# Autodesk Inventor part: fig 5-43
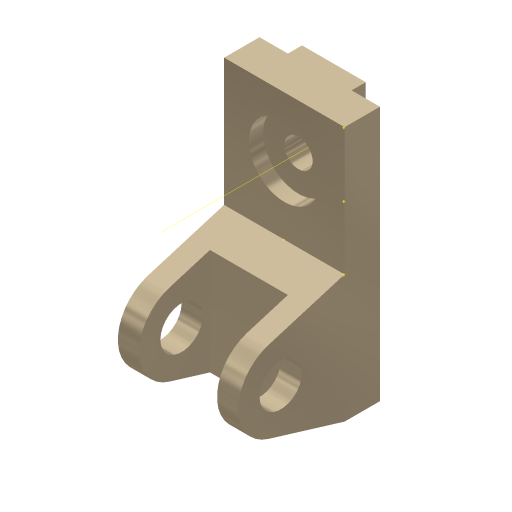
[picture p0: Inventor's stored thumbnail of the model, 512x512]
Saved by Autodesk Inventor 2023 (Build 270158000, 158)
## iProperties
Created: 2001-11
Part Number: fig 5-43
Document SubType Name: Modeling
Designer: Renu Muthoo
Density: 1 g/cm^3
Material: Generic
Appearance: Metal-Titanium (Polished)
Control State: 0
Master: False
Checked Out: False
Shininess: 65.0
Angle Display Precision: 2
Document Length Units: 11269
Document Angle Units: 11279
Document Time Units: 11290
Document Mass Units: 11283
Document Length Units Precision: 3
Document Angle Units Precision: 2
Density: 0.0
Volumn: 0.0
Area: 0.0
PropertySet Name: Model Information
Author: Renu Muthoo
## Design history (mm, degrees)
node "Sketch1"
sketch "Sketch2"
  geometry: L1 (33.257, 104.664)-(33.257, -75.336); L2 (33.257, -75.336)-(8.257, -75.336); L3 (8.257, -75.336)-(-45.451, -59.045); L4 (-45.451, -1.628)-(8.257, 14.664); L5 (8.257, 14.664)-(8.257, 104.664); L6 (8.257, 104.664)-(33.257, 104.664); C1 r 15 at (-36.743, -30.336); A1 r 30 centre (-36.743, -30.336) between (-45.451, -1.628) and (-45.451, -59.045)
  constraints: 12 end point, 2 centre point, 2 equal length, 2 parallel, 2 point on circle, 2 tangent, 1 coincident, 1 perpendicular, 1 vertical
  dimensions: "d0" = 180 distance of L1.start L1.end; "d1" = 30 radius of A1; "d2" = 25 distance of L5.end L1.start; "d3" = 45 distance from line of L2 A1.centre; "d4" = 70 distance from line of L1 A1.centre; "d5" = 30 diameter of C1
extrude "Extrusion1" new body sketch "Sketch2" distance "d6" = 85; taper "d7" = 0 deg
workplane "Work Plane1"
sketch "Sketch3"
  geometry: L1 (15, 62.364)-(70, 62.364); L2 (70, 62.364)-(70, -52.386); L3 (70, -52.386)-(15, -52.386); L4 (15, -52.386)-(15, 62.364); L5 (0, -45)-(0, -28.708) reference
  constraints: 8 end point, 2 parallel, 1 horizontal, 1 perpendicular
  dimensions: "d8" = 55 distance of L1.start L1.end; "d9" = 15 distance between parallel lines of L5 L4
extrude "Extrusion2" cut sketch "Sketch3" distance "d10" = 50; taper "d11" = 0 deg
sketch "Sketch4"
  geometry: L1 (0, 25)-(85, 25) reference; L2 (0, 0)-(0, 25) reference; L3 (20, 25)-(65, 25); L4 (65, 25)-(65, 35); L5 (65, 35)-(20, 35); L6 (20, 35)-(20, 25)
  constraints: 8 end point, 2 parallel, 1 horizontal, 1 perpendicular, 1 point on line
  dimensions: "d12" = 45 distance of L4.end L5.end; "d13" = 10 distance of L3.end L4.end; "d14" = 20 distance between parallel lines of L2 L6
extrude "Extrusion3" join sketch "Sketch4" stored distance "d15" = 50; taper "d16" = 0 deg
sketch "Sketch5"
  geometry: L1 (85, 0)-(85, 90) reference; L2 (0, 90)-(85, 90) reference; 1 further point
  dimensions: "d17" = 42 distance from line of L2 point (42.5, 48); "d18" = 42.5 distance from line of L1 point (42.5, 48)
hole "Hole1" sketch "Sketch5" at (42.5, 48) diameter "d19" = 20; stored, may be unused: countersink angle "d23" = 82 deg, drill point angle "d25" = 118 deg; dims "d20" = 6, "d21" = 50, "d22" = 10, "d24" = 8
workpoint "Work Point1"
workpoint "Work Point2"
workpoint "Work Point3"
workpoint "Work Point4"
workaxis "Work Axis2"
body "Solid1"
